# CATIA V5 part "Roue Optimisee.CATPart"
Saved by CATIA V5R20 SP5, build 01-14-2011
Part number: Roue Optimisée
Bounding box of the stored display mesh (mm): x -74.375 to 74.375, y 0 to 90, z -99.991 to 99.991
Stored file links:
  C:\Documents and Settings\ybellafdil\Bureau\Roue Optimisee.CATPart
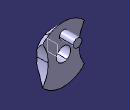
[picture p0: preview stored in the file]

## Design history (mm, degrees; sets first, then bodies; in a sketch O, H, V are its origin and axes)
Body1 (main body)
  Sketch1 on yz-plane, origin (0, 0, 0), H (0, 1, 0), V (0, 0, 1)
    point P1 (0, 25)
    line L1 (0, 25) -> (40, 25)
    line L2 (40, 25) -> (40, 100)
    line L3 (40, 100) -> (0, 60)
    point P4 (0, 60)
    line L4 (0, 60) -> (0, 25)
    angle L3 L2 = 45
    length L1 = 40
    distance L1 H = 25
    length L2 = 75
    coincidence: P1 V, P4 V
    horizontal: L1 H
    vertical: L2 V, L4 V
  Shaft1: profile Sketch1, axis Sketch1.H, angle 360
  Sketch2 on face of Shaft1 from Sketch1.L2, origin (0, 40, 0), H (-1, 0, 0), V (0, 0, 1)
    circle A1 centre (0, 60) radius 15
    point P1 (0, 60)
    radius A1 = 15
    distance P1 H = 60
    coincidence: P1 V
  Pad1: profile Sketch2, direction (0, 1, 0), length 50
  Sketch3 on face of Shaft1 from Sketch1.L2, origin (0, 40, 0), H (-1, 0, 0), V (0, 0, 1)
    circle A1 centre (-180, 0) radius 125
    point P1 (-180, 0)
    circle A2 centre (180, 0) radius 125
    point P2 (180, 0)
    radius A2 = 125
    radius A1 = 125
    distance P2 V = 180
    distance P1 V = 180
    coincidence: H P1, P2 H
  Pocket1: profile Sketch3, direction (0, -1, 0), length 50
